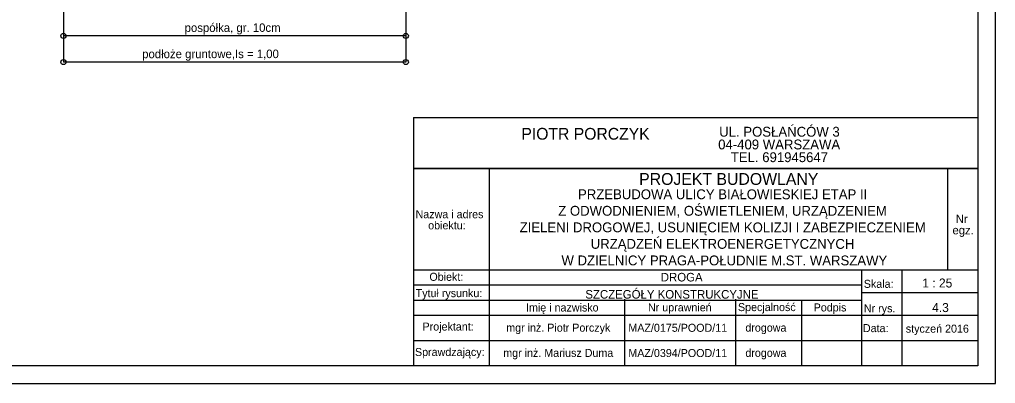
# Model space of a CAD drawing. Extents: x -219625893 to 7498339, y 5791790 to 5792761.
# Drawn here: x 7495383.6 to 7495527.2, y 5791790 to 5791843.4 of the extents above; entities that cross this region are included whole.
import ezdxf

# ---------------------------------------------------------------- set-up
doc = ezdxf.new("R2010")
doc.units = 0
for name, color, linetype in [('D_robocze_1', 7, 'Continuous'), ('Default', 7, 'Continuous'), ('Level 10', 7, 'Continuous'), ('wymiary', 7, 'Continuous')]:
    doc.layers.add(name, color=color, linetype=linetype)

msp = doc.modelspace()

# ---------------------------------------------------------------- linework, layer by layer
at = {"layer": 'D_robocze_1'}
for p, q in [((7495390.08, 5791871.88), (7495390.08, 5791837.19)), ((7495440.47, 5791872.63), (7495440.47, 5791837.19))]:
    msp.add_line(p, q, dxfattribs=at)
at = {"layer": 'Default'}
for p, q in [((7495441.59, 5791829.06), (7495441.59, 5791792.55)), ((7495441.59, 5791829.06), (7495524.65, 5791829.06)), ((7495524.65, 5791821.53), (7495441.59, 5791821.53)), ((7495441.59, 5791821.53), (7495524.65, 5791821.53)), ((7495452.75, 5791821.53), (7495452.75, 5791792.55)), ((7495520.17, 5791821.53), (7495520.17, 5791806.68)), ((7495441.59, 5791815.11), (7495441.59, 5791796.27)), ((7495441.59, 5791806.68), (7495524.65, 5791806.68)), ((7495507.53, 5791806.68), (7495507.53, 5791792.55)), ((7495513.48, 5791806.68), (7495513.48, 5791792.55)), ((7495441.59, 5791804.45), (7495507.53, 5791804.45)), ((7495507.53, 5791803.3), (7495524.65, 5791803.3)), ((7495441.59, 5791802.21), (7495507.53, 5791802.21)), ((7495472.63, 5791802.35), (7495472.63, 5791792.55)), ((7495488.98, 5791802.35), (7495488.98, 5791792.55)), ((7495498.7, 5791802.21), (7495498.7, 5791792.55)), ((7495498.7, 5791802.21), (7495498.7, 5791796.27)), ((7495441.59, 5791799.98), (7495507.53, 5791799.98)), ((7495507.53, 5791799.98), (7495524.65, 5791799.98)), ((7495441.59, 5791796.27), (7495507.53, 5791796.27)), ((7495507.53, 5791796.27), (7495524.65, 5791796.27))]:
    msp.add_line(p, q, dxfattribs=at)
at = {"layer": 'Level 10'}
for p, q in [((7495527.25, 5791789.95), (7495527.25, 5791938.45)), ((7495524.65, 5791935.85), (7495524.65, 5791792.55)), ((7495524.65, 5791792.55), (7495142.25, 5791792.55)), ((7495127.25, 5791789.95), (7495527.25, 5791789.95))]:
    msp.add_line(p, q, dxfattribs=at)
at = {"layer": 'wymiary'}
for points in [[(7495440.47, 5791841.04), (7495390.08, 5791841.04)], [(7495440.47, 5791837.19), (7495390.08, 5791837.19)]]:
    msp.add_lwpolyline(points, dxfattribs=at)
for centre in [(7495390.08, 5791841.04), (7495440.47, 5791841.04), (7495390.08, 5791837.19), (7495440.47, 5791837.19)]:
    msp.add_circle(centre, 0.375, dxfattribs=at)

# ---------------------------------------------------------------- texts
at = {"layer": 'Default'}
for s, height, rotation, p in [('PIOTR PORCZYK', 1.728, 359.9876, (7495457.48, 5791825.79)), ('UL. POSŁAŃCÓW 3', 1.4467, 359.9876, (7495486.59, 5791826.23)), ('04-409 WARSZAWA', 1.4467, 359.9876, (7495486.44, 5791824.36)), ('TEL. 691945647', 1.4467, 359.9876, (7495488.3, 5791822.49)), ('PROJEKT BUDOWLANY', 1.7398, 359.9876, (7495474.81, 5791819.14)), ('PRZEBUDOWA ULICY BIAŁOWIESKIEJ ETAP II', 1.4467, 359.9876, (7495465.81, 5791817.04)), ('Z ODWODNIENIEM, OŚWIETLENIEM, URZĄDZENIEM ', 1.4467, 359.9876, (7495462.9, 5791814.61)), ('Nazwa i adres', 1.178, 359.9999, (7495441.91, 5791814.24)), ('Nr ', 1.24, 359.9999, (7495521.41, 5791813.52)), ('obiektu:', 1.178, 359.9999, (7495443.76, 5791812.61)), ('ZIELENI DROGOWEJ, USUNIĘCIEM KOLIZJI I ZABEZPIECZENIEM ', 1.4467, 359.9876, (7495457.22, 5791812.18)), ('egz.', 1.24, 359.9999, (7495520.92, 5791811.87)), ('URZĄDZEŃ ELEKTROENERGETYCZNYCH', 1.4467, 359.9876, (7495467.68, 5791809.75)), ('W DZIELNICY PRAGA-POŁUDNIE M.ST. WARSZAWY', 1.4467, 359.9876, (7495463.38, 5791807.32)), ('Obiekt:', 1.178, 359.9999, (7495443.94, 5791805.04)), ('DROGA ', 1.256, 359.9876, (7495477.99, 5791804.95)), ('Skala:', 1.178, 359.9999, (7495507.87, 5791804.01)), ('1 : 25', 1.32, 359.9876, (7495516.48, 5791804.06)), ('Tytuł rysunku:', 1.178, 359.9999, (7495441.92, 5791802.64)), ('SZCZEGÓŁY KONSTRUKCYJNE', 1.2564, 359.9876, (7495466.89, 5791802.43)), ('Imię i nazwisko', 1.178, 359.9999, (7495458.16, 5791800.53)), ('Nr uprawnień', 1.178, 359.9999, (7495476.11, 5791800.55)), ('Specjalność', 1.178, 359.9999, (7495489.35, 5791800.59)), ('Podpis', 1.178, 359.9999, (7495500.49, 5791800.54)), ('Nr rys.', 1.178, 359.9999, (7495507.88, 5791800.41)), ('4.3', 1.32, 359.9876, (7495517.93, 5791800.45)), ('Projektant:', 1.178, 359.9999, (7495442.93, 5791797.73)), ('mgr inż. Piotr Porczyk', 1.178, 359.9876, (7495455.25, 5791797.57)), ('MAZ/0175/POOD/11', 1.178, 359.9876, (7495473.22, 5791797.55)), ('drogowa', 1.178, 359.9876, (7495490.44, 5791797.57)), ('Data:', 1.178, 359.9999, (7495507.74, 5791797.5)), ('styczeń 2016', 1.178, 359.9876, (7495514.05, 5791797.42)), ('Sprawdzający:', 1.178, 359.9999, (7495441.82, 5791793.99)), ('mgr inż. Mariusz Duma', 1.178, 359.9876, (7495454.81, 5791793.86)), ('MAZ/0394/POOD/11', 1.178, 359.9876, (7495473.22, 5791793.84)), ('drogowa', 1.178, 359.9876, (7495490.44, 5791793.86))]:
    msp.add_text(s, height=height, rotation=rotation, dxfattribs=at).set_placement(p)
at = {"layer": 'wymiary'}
for s, p in [('pospółka, gr. 10cm', (7495407.92, 5791841.62)), ('podłoże gruntowe,Is = 1,00 ', (7495401.67, 5791837.76))]:
    msp.add_text(s, height=1.25, rotation=0.0493, dxfattribs=at).set_placement(p)

doc.saveas('drawing.dxf')
